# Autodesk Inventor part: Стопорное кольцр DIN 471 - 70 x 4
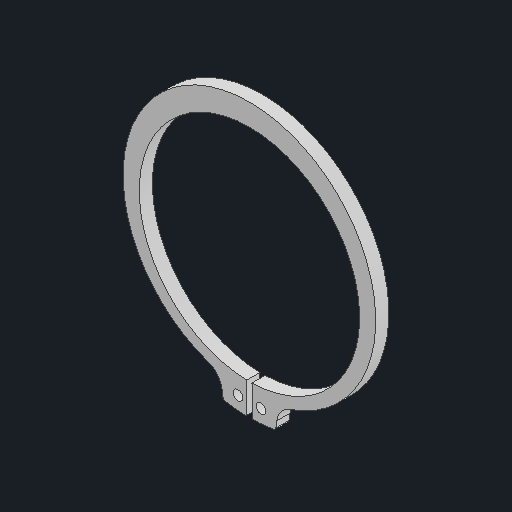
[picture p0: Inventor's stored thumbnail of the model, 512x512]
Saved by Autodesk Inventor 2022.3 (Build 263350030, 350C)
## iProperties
Created: 2020-09
Part Number: Стопорное кольцр DIN 471 - 70 x 4
Material: Типовые
Document SubType Name: Modeling
Designer: Карташов
Density: 1 g/cm^3
Appearance: По умолчанию
Title: D:\мои документы\Ирина\_WorldSkills\2020_09 ФНЧ\Module A\Участникам\GIVEN\Стопорное кольцр DIN 471 - 70 x 4.stp
Author: Дом
Sending System: Autodesk Inventor 2021
Preprocessor: ST-DEVELOPER v18.1
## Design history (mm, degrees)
feature "Твердое тело2"
node "Твердое тело1"
